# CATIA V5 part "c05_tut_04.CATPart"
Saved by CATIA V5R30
Part number: Part1
Bounding box of the stored display mesh (mm): x -150 to 0, y 0 to 54, z 0 to 16
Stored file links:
  D:\PROJECTS\CATIA V56R 2020\Resources\c05_catia_v5_6r2020_tut\c05_tut_04.CATPart
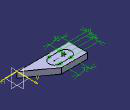
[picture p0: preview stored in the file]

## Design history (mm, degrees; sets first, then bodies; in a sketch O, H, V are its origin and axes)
Body1 (main body)
  Sketch1 on xy-plane, origin (0, 0, 0), H (1, 0, 0), V (0, 1, 0)
    line L1 (0, 0) -> (-150, 0)
    line L2 (-150, 0) -> (-150, 54)
    line L3 (-150, 54) -> (-75, 54)
    line L4 (-75, 54) -> (0, 0)
    length L2 = 54
    length L3 = 75
    length L1 = 150
    vertical: L2 V
    horizontal: L3 H, L1 H
  Pad1: profile Sketch1, direction (0, 0, 1), length 16
  Sketch2 on end face of Pad1, origin (0, 0, 16), H (1, 0, 0), V (0, 1, 0)
    construction line L1 (-114, 26) -> (-82, 26)
    point P1 (-114, 26)
    line L2 (-114, 42) -> (-82, 42)
    line L3 (-82, 10) -> (-114, 10)
    arc A1 centre (-82, 26) radius 16 from (-82, 42) to (-82, 10) cw
    arc A2 centre (-114, 26) radius 16 from (-114, 10) to (-114, 42) cw
    reference projected line E1 (-150, 0) -> (0, 0) from edge [face of Pad1 from Sketch1.L1 | end face of Pad1]
    reference projected line E2 (-150, 54) -> (-150, 0) from edge [face of Pad1 from Sketch1.L2 | end face of Pad1]
    distance L1 L2 = 16
    distance L3 E1 = 10
    length L2 = 32
    distance P1 E2 = 36
    horizontal: L1 H
    tangency: A1 L2, A2 L2, A1 L3, A2 L3
  Pad2: profile Sketch2, direction (0, 0, 1), length 3
  Sketch3 on face of Pad1 from Sketch1.L1, origin (0, 0, 0), H (1, 0, 0), V (0, 0, 1)
    line L1 (0, 0) -> (0, 50)
    arc A1 centre (-25, 50) radius 25 from (0, 50) to (-36.0939, 72.4037) ccw
    line L2 (-36.0939, 72.4037) -> (-150, 16)
    point P4 (-150, 16)
    line L3 (-150, 16) -> (-150, 0)
    point P5 (-150, 0)
    line L4 (-150, 0) -> (0, 0)
    reference projected line E1 (-150, 0) -> (-150, 16) from edge [face of Pad1 from Sketch1.L1 | face of Pad1 from Sketch1.L2]
    reference projected line E2 (-150, 16) -> (0, 16) from edge [face of Pad1 from Sketch1.L1 | end face of Pad1]
    radius A1 = 25
    length L1 = 50
    vertical: L1 V, L3 V
    tangency: A1 L1, L2 A1
    coincidence: P5 H, L3 E1, P4 E2
    horizontal: L4 H
  Pad3: profile Sketch3, direction (0, -1, 0), length 16
  Sketch4 on start face of Pad3, origin (0, 0, 0), H (-1, 0, 0), V (0, 0, 1)
    circle A1 centre (25, 50) radius 25
    reference projected arc E1 centre (25, 50) radius 25 from (37.6005, 71.5923) to (0, 50) ccw from edge [start face of Pad3 | face of Pad3 from Sketch3.A1]
    radius A1 = 25
    concentricity: A1 E1
  Pad4: profile Sketch4, direction (0, 1, 0), length 9
  Sketch5 on end face of Pad4, origin (0, 9, 0), H (-1, 0, 0), V (0, 0, 1)
    circle A1 centre (25, 50) radius 12.5
    reference projected circle E1 centre (25, 50) radius 25 from edge [face of Pad4 from Sketch4.A1 | end face of Pad4]
    radius A1 = 12.5
    concentricity: A1 E1
  Pocket1: profile Sketch5, direction (0, -1, 0), through (limit type 3)
  Sketch6 on end face of Pad2, origin (0, 0, 19), H (1, 0, 0), V (0, 1, 0)
    construction line L1 (-114, 26) -> (-82, 26)
    line L2 (-114, 34) -> (-82, 34)
    line L3 (-82, 18) -> (-114, 18)
    arc A1 centre (-82, 26) radius 8 from (-82, 34) to (-82, 18) cw
    arc A2 centre (-114, 26) radius 8 from (-114, 18) to (-114, 34) cw
    reference projected arc E1 centre (-114, 26) radius 16 from (-114, 42) to (-114, 10) ccw from edge [face of Pad2 from Sketch2.A2 | end face of Pad2]
    reference projected arc E2 centre (-82, 26) radius 16 from (-82, 10) to (-82, 42) ccw from edge [face of Pad2 from Sketch2.A1 | end face of Pad2]
    distance L2 L1 = 8
    horizontal: L1 H
    tangency: A1 L2, A2 L2, A1 L3, A2 L3
    concentricity: A2 E1, A1 E2
  Pocket2: profile Sketch6, direction (0, 0, -1), through (limit type 3)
